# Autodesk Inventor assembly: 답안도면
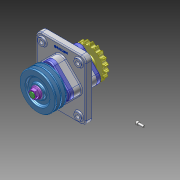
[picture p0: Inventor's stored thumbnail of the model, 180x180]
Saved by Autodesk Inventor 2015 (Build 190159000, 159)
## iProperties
Created: 2026-07
Part Number: 답안도면
Document SubType Name: Assembly
Designer: USER
Author: USER
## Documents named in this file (12)
- C:\Users\USER\Desktop\760705V1003\답안도면.iam
- C:\Users\USER\Desktop\760705V1003\본체.ipt
- C:\Users\USER\Desktop\760705V1003\가져온 구성요소\6각 구멍붙이 볼트 M6x16\6각 구멍붙이 볼트 M6x16.ipt
- C:\Users\USER\Desktop\760705V1003\가져온 구성요소\6각 플랜지 너트 M16\6각 플랜지 너트 M16.ipt
- C:\Users\USER\Desktop\760705V1003\가져온 구성요소\V-벨트풀리\V-벨트풀리.ipt
- C:\Users\USER\Desktop\760705V1003\가져온 구성요소\깊은 홈 볼 베어링 6206\깊은 홈 볼 베어링 6206.ipt
- C:\Users\USER\Desktop\760705V1003\가져온 구성요소\오일 실 30 45 8\오일 실 30 45 8.ipt
- C:\Users\USER\Desktop\760705V1003\가져온 구성요소\체인 스프로킷\체인 스프로킷.ipt
- C:\Users\USER\Desktop\760705V1003\가져온 구성요소\축\축.ipt
- C:\Users\USER\Desktop\760705V1003\가져온 구성요소\칼라\칼라.ipt
- C:\Users\USER\Desktop\760705V1003\가져온 구성요소\커버\커버.ipt
- C:\Users\USER\Desktop\760705V1003\가져온 구성요소\평행 키 6x6x20\평행 키 6x6x20.ipt
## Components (4 placed, 3 different names)
1. 6각 구멍붙이 볼트 M6x16:1
2. 6각 플랜지 너트 M16:1
3. V-벨트풀리:1
4. 6각 플랜지 너트 M16:2
